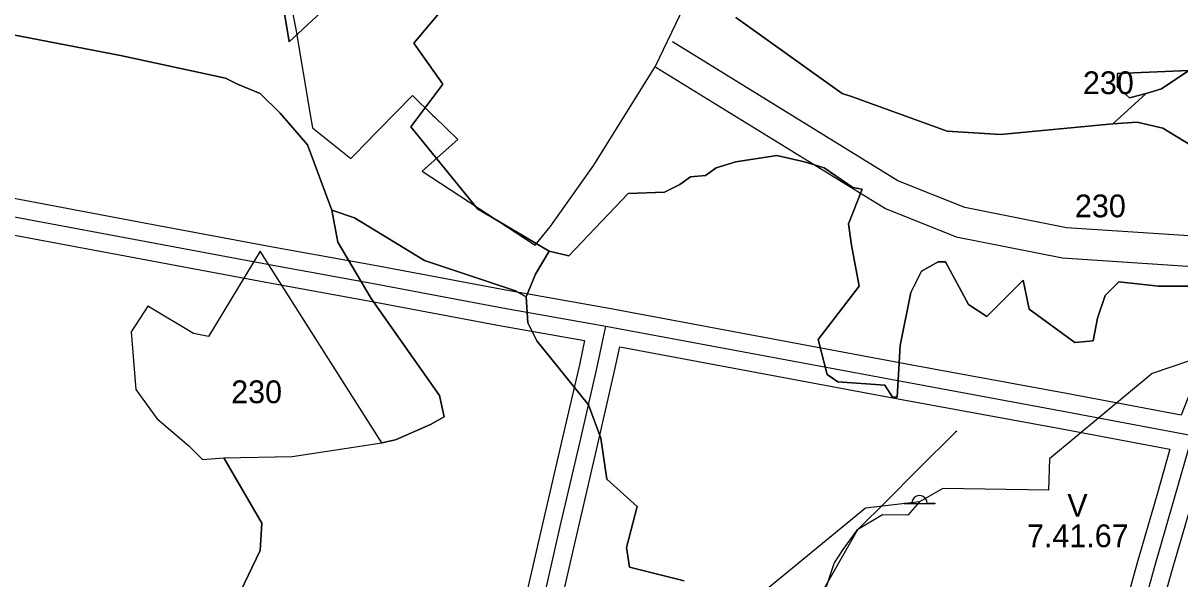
# Model space of a CAD drawing. Extents: x -694504 to -690518, y -983661 to -978958.
# Drawn here: x -692818 to -692057, y -981439 to -981074 of the extents above; entities that cross this region are included whole.
import ezdxf

# ---------------------------------------------------------------- set-up
doc = ezdxf.new("R2010")
doc.units = 0
for name, color, linetype in [('BPEJ', 7, 'Continuous'), ('lokální biocentra', 7, 'Continuous'), ('lokální biokoridory', 7, 'Continuous'), ('ochranné pásmo vedení', 7, 'Continuous'), ('třídy přednosti v ochraně ZP', 7, 'Continuous'), ('vedení NN', 7, 'Continuous'), ('vedení VN 35kV', 7, 'Continuous'), ('vodojem', 7, 'Continuous'), ('vodovodní řad', 7, 'Continuous')]:
    doc.layers.add(name, color=color, linetype=linetype)

msp = doc.modelspace()

# ---------------------------------------------------------------- linework, layer by layer
at = {"layer": 'BPEJ'}
for points in [[(-693048.4, -981115.81), (-693060.4, -981070.81), (-693081.4, -981038.81), (-693120.4, -980956.81), (-693102.4, -980936.81), (-693069.4, -980963.81), (-692971.4, -981028.81), (-692938.4, -981047.81), (-692843.4, -981077.81), (-692754.4, -981094.81), (-692685.4, -981109.81), (-692677.4, -981113.81), (-692662.4, -981119.81), (-692649.4, -981132.81), (-692631.4, -981153.81), (-692615.4, -981196.81), (-692615.4, -981196.81)], [(-692514.4, -981030.81), (-692561.4, -981086.81), (-692542.4, -981113.81), (-692563.4, -981141.81), (-692519.4, -981195.81), (-692472.4, -981223.81), (-692481.4, -981238.81), (-692487.4, -981253.81), (-692494.4, -981249.81), (-692554.4, -981229.81), (-692600.4, -981201.81), (-692615.4, -981196.81), (-692631.4, -981153.81), (-692649.4, -981132.81), (-692662.4, -981119.81), (-692677.4, -981113.81), (-692685.4, -981109.81), (-692754.4, -981094.81), (-692843.4, -981077.81)], [(-692045.4, -981246.81), (-692071.4, -981246.81), (-692097.4, -981243.81), (-692106.4, -981252.81), (-692111.4, -981267.81), (-692114.4, -981282.81), (-692126.4, -981283.81), (-692156.4, -981261.81), (-692160.4, -981242.81), (-692184.4, -981266.81), (-692196.4, -981258.81), (-692211.4, -981230.81), (-692216.4, -981230.81), (-692227.4, -981236.81), (-692234.4, -981250.81), (-692241.4, -981285.81), (-692243.4, -981319.81), (-692246.4, -981319.81), (-692251.4, -981311.81), (-692282.4, -981309.81), (-692289.4, -981304.81), (-692295.4, -981281.81), (-692268.4, -981246.81), (-692273.4, -981219.81), (-692275.4, -981205.81), (-692266.4, -981182.81), (-692272.4, -981181.81), (-692291.4, -981168.81), (-692304.4, -981164.81), (-692322.4, -981160.81), (-692349.4, -981164.81), (-692362.4, -981168.81), (-692369.4, -981173.81), (-692379.4, -981174.81), (-692386.4, -981179.81), (-692396.4, -981184.81), (-692420.4, -981185.81), (-692459.4, -981226.81), (-692472.4, -981223.81), (-692519.4, -981195.81), (-692563.4, -981141.81), (-692542.4, -981113.81), (-692561.4, -981086.81), (-692514.4, -981030.81)], [(-692649.4, -981049.81), (-692643.4, -981085.81), (-692586.4, -981032.81)], [(-692586.4, -981032.81), (-692643.4, -981085.81), (-692649.4, -981049.81)], [(-691979.4, -981069.81), (-692042.4, -981097.81), (-692051.4, -981104.81), (-692098.4, -981106.81), (-692098.4, -981115.81), (-692090.4, -981122.81), (-692079.4, -981119.81), (-692101.4, -981139.81), (-692175.4, -981146.81), (-692210.4, -981144.81), (-692273.4, -981121.81), (-692279.4, -981119.81), (-692349.4, -981069.81)], [(-692349.4, -981069.81), (-692279.4, -981119.81), (-692273.4, -981121.81), (-692210.4, -981144.81), (-692175.4, -981146.81), (-692101.4, -981139.81), (-692085.4, -981138.81), (-692068.4, -981142.81), (-691999.4, -981184.81)], [(-691861.4, -981072.81), (-691869.4, -981083.81), (-691896.4, -981104.81), (-691900.4, -981114.81), (-691898.4, -981121.81), (-691862.4, -981144.81), (-691860.4, -981153.81), (-691865.4, -981175.81), (-691886.4, -981234.81), (-691915.4, -981222.81), (-691961.4, -981198.81), (-691999.4, -981184.81), (-692068.4, -981142.81), (-692085.4, -981138.81), (-692101.4, -981139.81), (-692079.4, -981119.81), (-692069.4, -981116.81), (-692051.4, -981104.81), (-692042.4, -981097.81), (-691979.4, -981069.81)], [(-692383.4, -981440.81), (-692419.4, -981431.81), (-692421.4, -981418.81), (-692414.4, -981391.81), (-692434.4, -981373.81), (-692438.4, -981346.81), (-692446.4, -981324.81), (-692480.4, -981282.81), (-692486.4, -981270.81), (-692487.4, -981253.81), (-692481.4, -981238.81), (-692472.4, -981223.81), (-692459.4, -981226.81), (-692420.4, -981185.81), (-692396.4, -981184.81), (-692386.4, -981179.81), (-692379.4, -981174.81), (-692369.4, -981173.81), (-692362.4, -981168.81), (-692349.4, -981164.81), (-692322.4, -981160.81), (-692304.4, -981164.81), (-692291.4, -981168.81), (-692272.4, -981181.81), (-692266.4, -981182.81), (-692275.4, -981205.81), (-692273.4, -981219.81), (-692268.4, -981246.81), (-692295.4, -981281.81), (-692289.4, -981304.81), (-692282.4, -981309.81), (-692251.4, -981311.81), (-692246.4, -981319.81), (-692243.4, -981319.81), (-692241.4, -981285.81), (-692234.4, -981250.81), (-692227.4, -981236.81), (-692216.4, -981230.81), (-692211.4, -981230.81), (-692196.4, -981258.81), (-692184.4, -981266.81), (-692160.4, -981242.81), (-692156.4, -981261.81), (-692126.4, -981283.81), (-692114.4, -981282.81), (-692111.4, -981267.81), (-692106.4, -981252.81), (-692097.4, -981243.81), (-692071.4, -981246.81), (-692045.4, -981246.81)], [(-692615.4, -981196.81), (-692611.4, -981217.81), (-692589.4, -981254.81), (-692544.4, -981318.81), (-692541.4, -981332.81), (-692550.4, -981337.81), (-692573.4, -981347.81), (-692582.4, -981349.81), (-692662.4, -981223.81), (-692696.4, -981279.81), (-692706.4, -981277.81), (-692736.4, -981259.81), (-692747.4, -981276.81), (-692744.4, -981314.81), (-692730.4, -981333.81), (-692709.4, -981351.81), (-692700.4, -981360.81), (-692686.4, -981359.81), (-692661.4, -981402.81), (-692662.4, -981420.81), (-692675.4, -981447.81)], [(-692675.4, -981447.81), (-692662.4, -981420.81), (-692661.4, -981402.81), (-692686.4, -981359.81), (-692641.4, -981358.81), (-692582.4, -981349.81), (-692573.4, -981347.81), (-692550.4, -981337.81), (-692541.4, -981332.81), (-692544.4, -981318.81), (-692589.4, -981254.81), (-692611.4, -981217.81), (-692615.4, -981196.81), (-692600.4, -981201.81), (-692554.4, -981229.81), (-692494.4, -981249.81), (-692487.4, -981253.81), (-692487.4, -981253.81), (-692486.4, -981270.81), (-692480.4, -981282.81), (-692446.4, -981324.81), (-692438.4, -981346.81), (-692434.4, -981373.81), (-692414.4, -981391.81), (-692421.4, -981418.81), (-692419.4, -981431.81), (-692383.4, -981440.81)]]:
    msp.add_lwpolyline(points, dxfattribs=at)
msp.add_lwpolyline([(-692079.4, -981119.81), (-692090.4, -981122.81), (-692098.4, -981115.81), (-692098.4, -981106.81), (-692051.4, -981104.81), (-692069.4, -981116.81), (-692079.4, -981119.81)], close=True, dxfattribs=at)
at = {"layer": 'lokální biocentra'}
msp.add_lwpolyline([(-692650.89, -981018.02), (-692639.07, -981077.49), (-692629.6, -981133.7), (-692628.11, -981142.57), (-692602.75, -981162.74), (-692598.31, -981158.2), (-692594.87, -981154.68), (-692562.24, -981121.3), (-692548.84, -981134.3), (-692547.89, -981135.23), (-692532.45, -981150.2), (-692555.93, -981171.13), (-692481.43, -981219.81), (-692471.57, -981207.61), (-692442.92, -981167.09), (-692402.39, -981101.93), (-692383.73, -981063.02)], dxfattribs=at)
at = {"layer": 'lokální biokoridory'}
for points in [[(-692047.9, -981213.89), (-692131.91, -981208.27), (-692198.68, -981194.92), (-692242.79, -981177.37), (-692391.23, -981085.82)], [(-692402.05, -981102.64), (-692251, -981195.63), (-692204.38, -981214.17), (-692134.55, -981228.14), (-692048.96, -981233.86)]]:
    msp.add_lwpolyline(points, dxfattribs=at)
at = {"layer": 'ochranné pásmo vedení'}
for points in [[(-691792.72, -980931.21), (-691822.1, -980903.17), (-691864.46, -980860.54), (-691913.85, -980906.25), (-691959.7, -980946.13), (-692009.06, -980988.9), (-692004.73, -981064.6), (-692001.73, -981131.67), (-691997.92, -981186.06), (-692018.89, -981236.58), (-692039.93, -981289.69), (-692056.39, -981331.65), (-692131.85, -981317.45), (-692234.86, -981298.45), (-692432.9, -981261.44), (-692500.89, -981249.44), (-692585.86, -981233.45), (-692655.55, -981220.75), (-692739.96, -981204.97), (-692834.02, -981187.35)], [(-692838.35, -981210.45), (-692744.28, -981228.07), (-692659.81, -981243.86), (-692590.14, -981256.55), (-692505.11, -981272.56), (-692449.04, -981282.45), (-692452.47, -981298.46), (-692463.45, -981346.36), (-692476.45, -981402.36), (-692490.45, -981463.37), (-692501.44, -981511.34), (-692514.44, -981566.34), (-692530.37, -981635.87), (-692542.33, -981688.04), (-692492.58, -981735.69)], [(-692476.97, -981718.1), (-692516.45, -981680.3), (-692507.47, -981641.12), (-692491.56, -981571.66), (-692478.56, -981516.66), (-692467.55, -981468.63), (-692453.55, -981407.64), (-692440.55, -981351.64), (-692429.53, -981303.54), (-692425.91, -981286.65), (-692239.14, -981321.55), (-692136.15, -981340.55), (-692063.84, -981354.16), (-692072.29, -981383.76), (-692085.31, -981428.8), (-692098.34, -981475.94), (-692108.32, -981513.84), (-692122.09, -981560.59)], [(-692098.78, -981564.62), (-692085.68, -981520.16), (-692075.66, -981482.06), (-692062.69, -981435.2), (-692049.71, -981390.24), (-692040.57, -981358.27), (-691970.98, -981369.58), (-691892.99, -981383.58), (-691578.35, -981435.35), (-691505.97, -981436.12), (-691403.79, -981436.1), (-691320.85, -981435.75), (-691226.93, -981433.75), (-691115.11, -981434.75), (-691018, -981435.75), (-690919.94, -981434.75), (-690865, -981434.75), (-690798.01, -981434.75), (-690720.4, -981434.84), (-690660.99, -981434.75), (-690632.73, -981444.66)]]:
    msp.add_lwpolyline(points, dxfattribs=at)
at = {"layer": 'vedení NN'}
for points in [[(-692205.03, -981342.7), (-692204.03, -981341.91), (-692230.09, -981367.77)], [(-692304.18, -981468.07), (-692286.37, -981436.95), (-692269.09, -981406.97), (-692250.04, -981388), (-692230.09, -981367.77)], [(-692304.18, -981468.07), (-692286.37, -981436.95), (-692269.09, -981406.97), (-692250.04, -981388), (-692230.09, -981367.77)]]:
    msp.add_lwpolyline(points, dxfattribs=at)
at = {"layer": 'vedení VN 35kV'}
for points in [[(-692109.51, -981559.46), (-692097, -981517), (-692087, -981479), (-692074, -981432), (-692061, -981387), (-692049, -981345), (-692029, -981294), (-692008, -981241), (-691986, -981188), (-691990, -981131), (-691993, -981064), (-691997, -980994), (-691952, -980955), (-691906, -980915), (-691864.8, -980876.87), (-691830.33, -980911.56), (-691803.29, -980937.37)], [(-692836.19, -981198.9), (-692742.12, -981216.52), (-692657.68, -981232.3), (-692588, -981245), (-692503, -981261), (-692435, -981273), (-692237, -981310), (-692134, -981329), (-692049, -981345), (-691969, -981358), (-691891, -981372), (-691577.33, -981423.61), (-691505.91, -981424.37), (-691403.82, -981424.35), (-691321, -981424), (-691227, -981422), (-691115, -981423), (-691018, -981424), (-690920, -981423), (-690865, -981423), (-690798, -981423), (-690720.41, -981423.09), (-690659, -981423), (-690630.93, -981432.84)], [(-692490.22, -981721.68), (-692529.39, -981684.17), (-692518.92, -981638.49), (-692503, -981569), (-692490, -981514), (-692479, -981466), (-692465, -981405), (-692452, -981349), (-692441, -981301), (-692435, -981273)]]:
    msp.add_lwpolyline(points, dxfattribs=at)
at = {"layer": 'vodojem'}
for p, q in [((-692238.65, -981389.6), (-692233.64, -981389.6)), ((-692238.65, -981390.13), (-692238.65, -981389.6)), ((-692238.65, -981390.13), (-692238.65, -981389.6)), ((-692238.65, -981389.6), (-692233.64, -981389.6)), ((-692218.54, -981390.13), (-692238.65, -981390.13)), ((-692218.54, -981390.13), (-692238.65, -981390.13)), ((-692223.57, -981389.59), (-692218.54, -981389.59)), ((-692223.57, -981389.59), (-692218.54, -981389.59)), ((-692218.54, -981389.59), (-692218.54, -981390.13)), ((-692218.54, -981389.59), (-692218.54, -981390.13))]:
    msp.add_line(p, q, dxfattribs=at)
msp.add_ellipse((-692228.61, -981389.58), major_axis=(-5.03, 0), ratio=0.990986, start_param=3.141359, end_param=6.28742, dxfattribs=at)
msp.add_ellipse((-692228.61, -981389.58), major_axis=(-5.03, 0), ratio=0.990986, start_param=3.141359, end_param=6.28742, dxfattribs=at)
at = {"layer": 'vodovodní řad'}
for points in [[(-691952.28, -981239.87), (-691994.16, -981283.53), (-692016.03, -981284.05), (-692075.58, -981304.29), (-692142.96, -981360.36), (-692143.71, -981380.97), (-692213.37, -981379.85), (-692228.6, -981388.76), (-692264.18, -981392.95), (-692318.32, -981437.42), (-692356, -981468.38)], [(-692228.6, -981388.76), (-692236.29, -981397.46), (-692252.88, -981397.28), (-692269.84, -981407.35), (-692278.97, -981420.21), (-692284.73, -981428.92), (-692289.95, -981444.58)]]:
    msp.add_lwpolyline(points, dxfattribs=at)

# ---------------------------------------------------------------- texts
at = {"layer": 'třídy přednosti v ochraně ZP'}
for s, p in [('230', (-692121.07, -981120.34)), ('230', (-692126.32, -981201.41)), ('230', (-692681.57, -981323.79)), ('V', (-692131.34, -981398.58)), ('7.41.67', (-692157.89, -981418.58))]:
    msp.add_text(s, height=15, dxfattribs=at).set_placement(p)

doc.saveas('drawing.dxf')
